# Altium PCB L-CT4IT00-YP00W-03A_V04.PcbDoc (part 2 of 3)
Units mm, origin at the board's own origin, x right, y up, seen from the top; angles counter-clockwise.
Board outline 52 x 31.8 mm, 4 copper layers (Top Layer, Layer 1, Layer 2, Bottom Layer), stack 1.288 mm thick; 160 components, 112 nets, 631 pads, 1087 vias.
Unrouted connection lines stored in the file: 130.
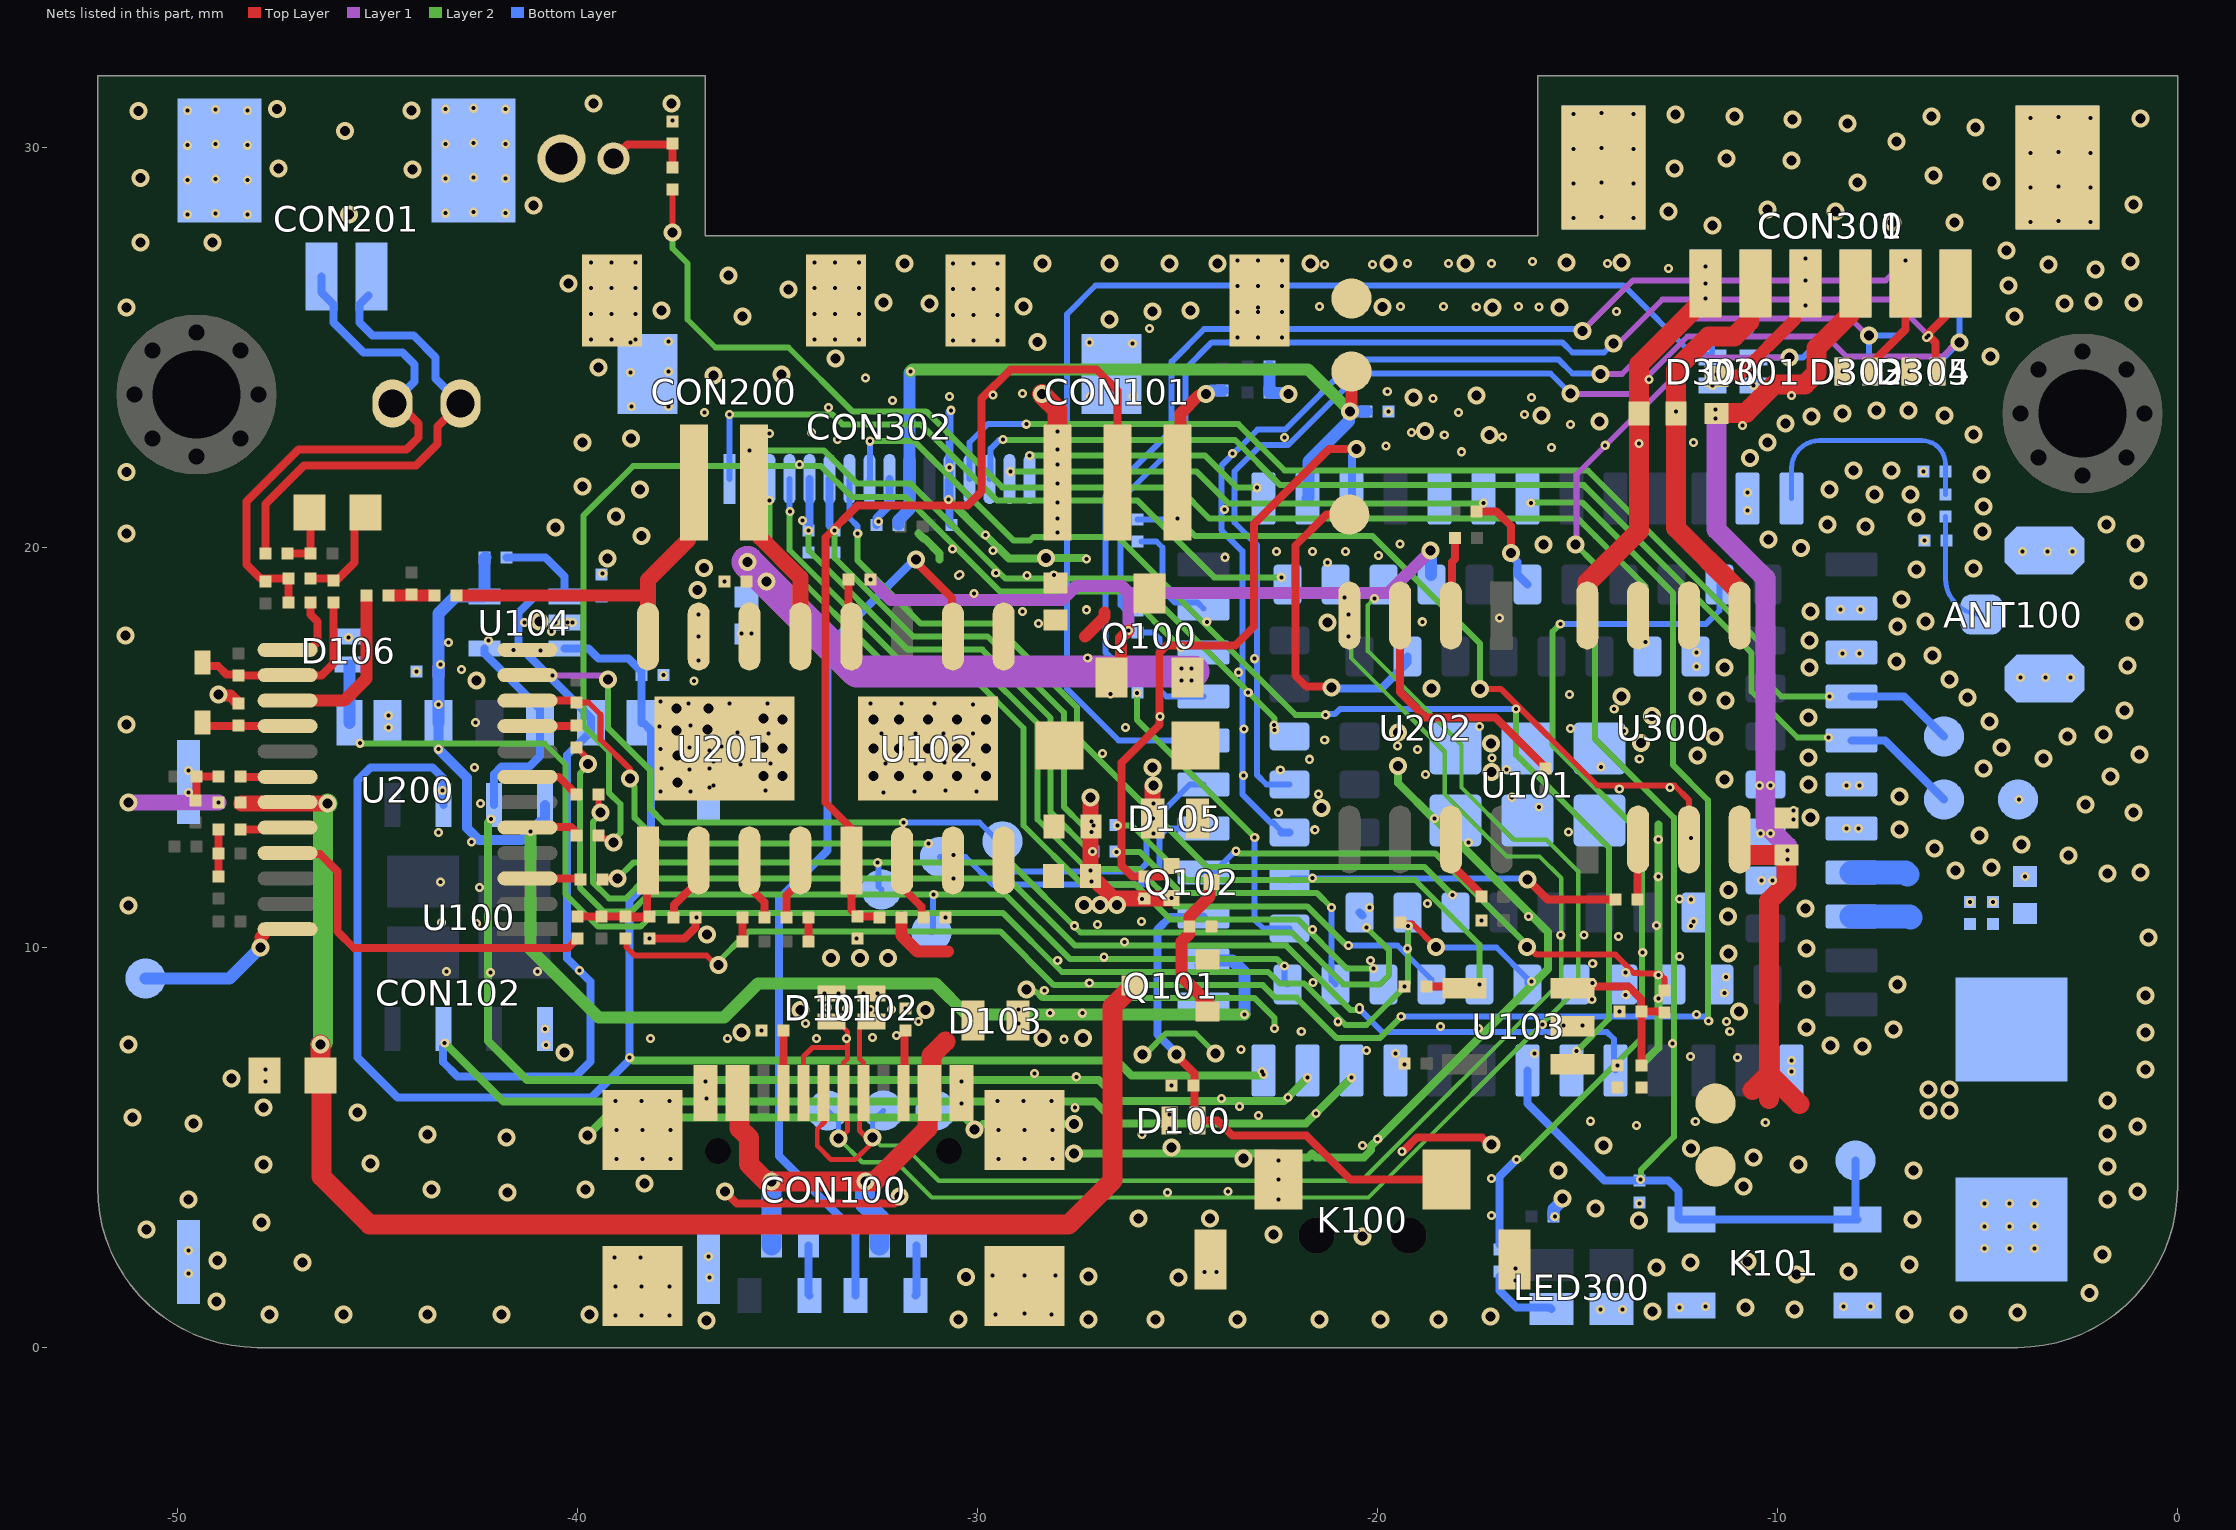
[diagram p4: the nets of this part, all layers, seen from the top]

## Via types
v1: diameter 0.23, hole 0.1, Top Layer to Layer 1, tented both sides, 385 vias
v2: diameter 0.45, hole 0.25, Top Layer to Bottom Layer, tented both sides, 379 vias
v3: diameter 0.23, hole 0.1, Layer 2 to Bottom Layer, tented both sides, 323 vias

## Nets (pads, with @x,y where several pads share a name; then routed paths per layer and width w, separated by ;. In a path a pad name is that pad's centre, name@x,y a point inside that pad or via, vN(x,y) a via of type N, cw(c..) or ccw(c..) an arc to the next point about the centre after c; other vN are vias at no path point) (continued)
GND: ANT100.2 ANT100.3 C100.1 C101.1 C102.2 C103.1 C104.1 C105.1 C106.1 C107.1 C109.1 C110.1 C111.1 C112.1 C113.1 C114.1 C115.1 C116.1 C117.1 C118.1 C202.1 C203.1 C204.1 C205.1 C206.1 C215.1 C218.2 C300.1 C301.1 C303.2 C304.1 C305.2 C306.2 C307.1 C308.1 CON100.0 CON100.A1B12 CON100.B1A12 CON101.0 CON101.3 CON102.0@-36.725,2.133 CON102.0@-36.725,14.132 CON102.0@-49.725,2.133 CON102.0@-49.725,14.132 CON102.5 CON200.0 CON201.0 CON300.0 CON300.4 CON301.0 CON301.1 CON301.3 CON302.0@-26.65,24.338 CON302.0@-38.25,24.338 CON302.9 CON302.12 D100.A D101.A D102.A D103.A D105.A D106.A D300.A D301.A D302.A D303.A D304.A D305.A K100.0@-16.575,2.2 K100.0@-24.175,2.2 K100.1 K101.1 K101.2 K300.1 LED300.2 Q102.S R107.2 R108.2 R109.2 R111.2 R114.1 R115.1 R117.1 R120.1 R208.1 TP300.1 TP301.1 TP302.1 TP303.1 U100.1 U101.1 U101.10 U101.27 U101.34 U101.36 U101.37 U101.40 U101.41 U101.45 U101.46 U101.47 U101.48 U101.70 U101.71 U101.72 U101.73 U101.88 U101.89 U101.90 U101.91 U101.92 U101.93 U101.94 U101.95 U102.0 U102.3 U103.2 U104.2 U200.12 U201.0 U201.7 U202.4 U300.6 U300.7 | length 83.4
  Top Layer w0.2: v1(-38.2,10.225) -37.325,10.225 -37.05,10.5 C202.1@-37.05,10.75 ; v2(-36.314,3.9) -36.017,3.603 -32.072,3.603 v2@-31.95,3.725 ; v1(-28.577,6.852) v1@-28.569,6.852 ; v2(-27.583,5.589) v2@-27.566,5.606 ; v1@-27.566,5.991 v1(-27.56,5.997) ; v1@-19.371,4.9 -19.371,4.906 -19.362,4.915 -19.353,4.915 -19.018,5.25 -17.392,5.25 -17.217,5.075 v2(-17.15,5.075)
  Top Layer w0.3: v2(-48.974,16.325) -48.945,16.296 -48.671,16.296 C204.1@-48.475,16.1 ; C304.1@-11.525,24.275 -11.494,24.306 -10.957,24.306 -9.55,25.713 -9.55,26.35 CON300.4@-9.3,26.6
  Top Layer w0.4: v2(-27.176,13.751) -27.176,11.801 -26.6,11.225 -25.161,11.225 v1(-25.15,11.236) ; D105.A@-25.621,13.226 -25.621,14.029 v2(-25.6,14.05)
  Top Layer w0.5: v2(-28.391,23.834) -28,23.443 CON101.3@-28,21.625 ; D105.A@-25.621,13.016 D105.A@-25.621,13.226
  Layer 1 w0.4: v2@-51.175,13.625 v1(-48.975,13.625)
  Layer 2 w0.15: v2(-28.775,8.95) -28.718,8.893 -28.538,8.893 -28.378,8.732 -23.07,8.732 -22.58,8.243 -22.58,7.98 v3(-22.575,7.975) ; v2@-25.754,7.386 -25.29,7.85 -24.55,7.85 v2(-24.05,7.35)
  Layer 2 w0.2: v2(-39.75,5.3) -39.297,5.753 -30.317,5.753 -30.014,5.45 -30.007,5.45 -29.868,5.589 v2(-27.583,5.589) ; v3@-32.804,24.247 v3(-32.798,24.241) ; -31.475,20.35 -31.351,20.226 -31.321,20.226 -30.949,19.854 -30.949,19.7 ; v3(-30.728,21.202) -29.847,20.321 -29.816,20.321 v3@-29.816,20.316 ; v3@-29.808,20.321 -29.209,19.723 -28.301,19.723 v2(-28.29,19.734) -27.306,19.735 -27.285,19.714 v3(-27.277,19.714) ; v2(-27.583,4.85) -22.575,4.85 -22.479,4.754 -21.731,4.754 -21.635,4.85 -21.54,4.754 -20.344,4.754 -20.164,4.934 -20.164,5.035 -19.996,5.203 v3(-19.996,5.211) -19.989,5.211 -15.74,9.46 -15.74,10.391 -18.565,13.217 v3@-18.585,13.217 ; v3@-26.685,16.343 v3(-26.679,16.337) ; v2(-19.483,14.532) -19.483,14.108 v3@-18.588,13.213 ; -13.4,7.075 -12.981,7.494 v3(-12.981,8.728) v3(-12.981,9.314) v3(-12.981,11.77) v3(-12.981,12.704) -12.976,12.71 -12.976,13.072
  Bottom Layer w0.2: C306.2@-32.525,20.563 -32.525,20.739 -32.2,21.064 CON302.9@-32.2,21.712 ; v3(-30.728,21.202) -30.728,21.684 CON302.12@-30.7,21.712 -30.7,20.787 -30.7,20.613 C305.2@-30.65,20.563 ; CON302.12@-30.7,21.712 -30.7,23.388 -30.664,23.423 v3(-30.664,23.431) ; CON301.0@-15.25,28.6 CON301.0@-14.35,29.5
  Bottom Layer w0.3: R114.1@-22.7,24.525 C112.1@-22.7,23.875 -22.687,23.862 -22.252,23.862 v2(-22.223,23.833) ; C303.2@-15.593,3.271 C303.2@-15.6,3.275 C303.2@-15.6,3.275 -15.6,3.459 -15.375,3.684 v2(-15.375,3.725)
  other v1: -39.05,0.8 -38.4,0.8 -37.7,0.8 -29.55,0.825 -28.15,0.825 -28.825,0.85 -39.05,1.525 -38.4,1.525 -37.7,1.525 -16.55,1.675 -29.625,1.8 -28.825,1.8 -28.05,1.8 -24.324,1.886 -24.02,1.886 -16.55,1.975 -39.075,2.25 -38.425,2.25 -17.15,3.3 -22.475,3.7 -25.25,3.875 -23.74,3.9 -22.475,4.2 -17.15,4.225 -22.475,4.675 -39.02,4.713 -38.37,4.713 -37.67,4.713 -29.48,4.713 -28.83,4.713 -28.13,4.713 -19.385,4.9 -20.379,5.048 -25.89,5.323 -39.02,5.437 -38.37,5.437 -37.67,5.437 -29.48,5.437 -28.83,5.437 -28.13,5.437 -25.2,5.475 -22.975,5.8 -25.2,5.825 -21.535,5.85 -23.45,6.025 -30.4,6.1 -39.045,6.162 -38.395,6.162 -37.695,6.162 -29.505,6.162 -28.855,6.162 -28.155,6.162 -36.775,6.225 -23.9,6.225 -22.235,6.25 -25.15,6.55 -47.8,6.65 -36.8,6.65 -30.4,6.65 -27.531,6.769 -22.885,6.9 -47.8,6.95 -14,7.05 -19.326,7.075 -11.001,7.25 -12.176,7.275 -16.075,7.35 -20.275,7.425 -23.41,7.45 -12.626,7.6 -27.836,7.706 -35.4,7.925 -17.476,7.975 -18.426,8.025 -15.35,8.05 -14.875,8.05 -15.876,8.075 -28.975,8.1 -20.987,8.145 -11.275,8.15 -12.025,8.325 -28.182,8.362 -27.38,8.358 -13.95,8.4 -28.975,8.45 -31.8,8.475 -20.451,8.5 -33.825,8.85 -33.475,8.85 -32.85,8.85 -32.5,8.85 -28.331,8.925 -19.325,9.025 -27.207,9.116 -21.615,9.125 -16.151,9.15 -42.175,9.375 -43.275,9.4 -41,9.4 -39.95,9.425 -27.995,9.677 -20.176,9.675 -26.839,9.758 -12.451,9.775 -13.371,9.876 -19.251,9.969 -26.324,10.136 -33.025,10.225 -13.976,10.275 -15.421,10.309 -14.837,10.316 -21.626,10.45 -27.577,10.542 -13.026,10.55 -27.002,10.574 -42.525,10.6 -43.4,10.625 -25.903,10.652 -12.101,10.65 -17.4,10.675 -37.025,10.75 -30.8,10.75 -16.226,10.775 -20.201,11 -18.751,11.1 -12.451,11.213 -25.891,11.218 -42.45,11.5 -43.425,11.636 -27.15,11.65 -30.6,11.725 -21.626,11.735 -27.175,11.925 -30.6,12.313 -42.649,12.639 -25.6,12.85 -43.475,12.875 -27.15,12.892 -21.568,12.943 -27.15,13.15 -9.6,13.2 -25.611,13.226 -22.476,13.375 -9.6,13.425 -42.425,13.6 -25.6,13.6 -21.473,13.834 -32.35,13.875 -37.925,13.9 -37.175,13.9 -31.575,13.9 -30.025,13.9 -43.375,13.925 -35.3,13.925 -30.8,13.925 -36.6,14.05 -23.351,14.3 -22.431,14.44 -37.2,14.45 -37.9,14.475 -42.575,14.5 -35.925,14.575 -30.1,14.575 -35.175,14.6 -32.3,14.6 -31.55,14.6 -30.825,14.625 -36.6,14.65 -21.7,14.705 -26.875,14.85 -43.475,14.957 -37.925,14.957 -37.2,15 -36.4,15.025 -35.225,15.35 -32.4,15.35 -31.55,15.35 -30.85,15.35 -30.11,15.35 -36,15.375 -23.336,15.467 -26.3,15.5 -37.95,15.525 -37.175,15.55 -22.586,15.563 -42.55,15.625 -43.475,16.075 -30.11,16.075 -37.225,16.1 -36.2,16.1 -35.25,16.1 -32.675,16.1 -31.9,16.1 -31.075,16.1 -37.925,16.15 -23.232,16.378 -23.479,16.881 -42.9,16.95 -43.425,17.075 -36.975,17.175 -23.078,17.222 -40.925,17.425 -41.6,17.442 -43.225,17.625 -42.225,17.675 -36.97,17.775 -20.726,17.775 -40.65,17.9 -41.325,18.125 -40.125,18.125 -24.269,18.143 -36.97,18.325 -20.726,18.325 -36.325,19.15 -28.762,19.304 -28.094,19.315 -30.437,19.329 -29.543,19.36 -21.251,19.625 -23.816,19.757 -19.976,19.8 -29.611,19.929 -30.626,19.963 -19.436,20.092 -28,20.375 -34.376,20.675 -28,20.725 -23.826,20.95 -28,21.125 -28,21.6 -30.701,22 -34.451,22.075 -28,22.075 -23.626,22.35 -28,22.45 -22.326,22.75 -28,22.9 -33.726,23.5 -32.126,23.675 -30.701,23.775 -11.525,24.325 -30.615,25.175 -30.1,25.175 -29.5,25.175 -39.665,25.2 -39.15,25.2 -38.55,25.2 -34.075,25.2 -33.56,25.2 -32.96,25.2 -23.5,25.25 -22.985,25.25 -22.385,25.25 -30.615,25.817 -30.1,25.817 -29.5,25.817 -39.665,25.842 -39.15,25.842 -38.55,25.842 -34.075,25.842 -33.56,25.842 -32.96,25.842 -23.5,25.892 -22.985,25.892 -22.385,25.892 -30.615,26.458 -30.1,26.458 -29.5,26.458 -39.665,26.483 -39.15,26.483 -38.55,26.483 -34.075,26.483 -33.56,26.483 -32.96,26.483 -23.5,26.533 -22.985,26.533 -22.385,26.533 -30.615,27.1 -30.1,27.1 -29.5,27.1 -39.665,27.125 -39.15,27.125 -38.55,27.125 -34.075,27.125 -33.56,27.125 -32.96,27.125 -23.5,27.175 -22.985,27.175 -22.385,27.175 -37.625,30.675
  other v2: -36.775,0.675 -30.475,0.7 -27.226,0.7 -25.55,0.7 -23.5,0.7 -21.45,0.7 -19.925,0.7 -18.475,0.7 -17.175,0.775 -47.7,0.825 -45.85,0.825 -43.75,0.825 -41.9,0.825 -39.7,0.825 -6.825,0.825 -5.475,0.825 -4,0.875 -13.125,0.9 -9.575,0.95 -10.8,1 -49.025,1.15 -2.2,1.36 -30.292,1.757 -24.98,1.751 -27.224,1.775 -9.525,1.825 -8.225,1.9 -13.025,2 -6.7,2.075 -12.18,2.12 -46.875,2.125 -49,2.175 -10.75,2.15 -1.875,2.325 -20.375,2.775 -22.6,2.825 -50.775,2.95 -47.9,3.125 -13.463,3.175 -6.625,3.2 -25.975,3.225 -24.184,3.219 -14.55,3.475 -49.725,3.7 -1.75,3.7 -31.95,3.78 -41.75,3.875 -1,3.9 -43.65,3.95 -39.804,3.95 -10.85,4.025 -38.325,4.1 -15.475,4.425 -6.6,4.425 -1.75,4.525 -47.85,4.575 -9.475,4.575 -45.175,4.6 -23.351,4.725 -10.6,4.75 -12.168,4.978 -25.15,5 -14.35,5.05 -41.775,5.25 -43.75,5.325 -1.75,5.35 -30.075,5.45 -1,5.525 -49.6,5.6 -51.125,5.75 -45.5,5.875 -47.85,6 -1.75,6.175 -48.65,6.725 -0.8,6.95 -25.875,7.325 -40.325,7.375 -7.875,7.525 -8.675,7.55 -51.225,7.575 -27.365,7.737 -28.375,7.741 -35.9,7.875 -0.8,7.875 -7.1,7.95 -9.275,8 -10.962,8.404 -34.425,8.441 -31.3,8.441 -0.8,8.8 -9.275,8.95 -7,9.075 -33.658,9.738 -32.943,9.733 -32.241,9.738 -11.226,9.856 -9.275,9.975 -0.725,10.25 -36.762,10.325 -11.235,10.771 -9.3,10.975 -51.225,11.051 -27.335,11.06 -26.94,11.06 -26.512,11.06 -11.225,11.44 -1.75,11.85 -0.925,11.875 -5.55,11.925 -4.65,12 -2.725,12.3 -6.075,12.475 -3.9,12.575 -4.95,12.8 -6.95,12.95 -9.175,13.25 -1.1,13.375 -21.4,13.483 -2.3,13.575 -51.225,13.625 -6.95,13.775 -9.225,14.075 -37.5,14.125 -11.325,14.2 -35.35,14.283 -34.881,14.283 -32.597,14.283 -31.965,14.283 -31.24,14.283 -30.515,14.283 -29.79,14.283 -1.675,14.275 -17.152,14.39 -4.85,14.475 -25.625,14.5 -3.35,14.725 -9.225,14.75 -12,14.795 -37.5,14.8 -0.95,14.825 -34.881,14.975 -32.597,14.975 -31.965,14.975 -31.24,14.975 -30.515,14.975 -29.79,14.975 -35.35,15 -4.4,15 -17.163,15.102 -13.417,15.108 -11.575,15.275 -2.75,15.275 -1.85,15.325 -19.483,15.377 -37.525,15.425 -36.75,15.45 -51.275,15.575 -4.7,15.65 -34.881,15.7 -32.597,15.7 -31.965,15.7 -31.24,15.7 -30.515,15.7 -29.79,15.7 -35.35,15.725 -9.225,15.751 -13.135,15.786 -1.325,15.925 -37.525,15.975 -36.725,15.975 -11.3,16.175 -5.25,16.25 -13.897,16.278 -12,16.275 -18.65,16.475 -42.525,16.675 -5.7,16.7 -11.325,17 -9.2,17 -1.25,17.05 -7.025,17.15 -6.125,17.3 -9.2,17.675 -51.3,17.8 -7,18.025 -21.25,18.125 -40.95,18.15 -6.3,18.15 -1.075,18.15 -9.175,18.4 -6.9,18.7 -37.002,18.942 -0.975,19.175 -6.525,19.45 -36.842,19.493 -5.1,19.475 -39.254,19.731 -9.416,19.987 -15.85,20.075 -1.05,20.1 -10.225,20.2 -38.402,20.292 -51.275,20.35 -4.875,20.4 -40.55,20.5 -7.8,20.525 -8.75,20.575 -1.775,20.575 -6.525,20.75 -39.041,20.772 -4.85,21.025 -7.575,21.325 -6.675,21.325 -38.441,21.45 -8.7,21.45 -39.875,21.525 -4.9,21.825 -51.281,21.884 -8.1,21.925 -7.15,21.925 -10.691,22.238 -39.875,22.625 -10.25,22.625 -38.658,22.727 -17.197,22.811 -5.1,22.825 -18.814,22.916 -9.8,23.1 -14.45,23.15 -9.15,23.275 -15.9,23.3 -5.825,23.3 -8.375,23.35 -7.525,23.425 -6.725,23.425 -19.1,23.75 -17.531,23.799 -36.6,24.3 -34.9,24.325 -39.475,24.5 -33.55,24.725 -4.675,24.775 -28.495,25.136 -26.7,25.7 -35.875,25.775 -4.075,25.775 -25.625,25.9 -37.9,25.925 -24.675,25.925 -15.445,25.996 -51.273,26.001 -28.855,26.025 -19.876,26.008 -17.123,26.002 -31.2,26.1 -2.825,26.1 -32.35,26.125 -1.1,26.125 -2.1,26.15 -34.725,26.45 -4.225,26.55 -40.225,26.6 -36.225,26.8 -2.05,26.95 -3.225,27.075 -31.825,27.1 -28.375,27.1 -26.7,27.1 -25.2,27.1 -24,27.1 -21.675,27.1 -19.725,27.1 -17.8,27.1 -15.275,27.125 -13.9,27.125 -1.175,27.15 -4.275,27.425 -50.929,27.62 -49.125,27.625 -11.625,28.05 -7.125,28.125 -5.575,28.125 -45.714,28.327 -12.725,28.4 -8.55,28.4 -10.25,28.45 -41.1,28.55 -1.1,28.575 -8,29.125 -4.65,29.15 -50.921,29.243 -6.1,29.3 -44.125,29.45 -47.475,29.475 -12.575,29.475 -9.65,29.675 -11.275,29.725 -7.025,30.15 -45.812,30.416 -5.05,30.5 -8.25,30.6 -9.625,30.7 -0.925,30.725 -11.075,30.775 -6.15,30.775 -12.55,30.825 -50.973,30.914 -44.15,30.925 -47.508,30.958 -39.6,31.1 -37.65,31.1
  other v3: -14.425,0.95 -13.875,0.95 -12.45,1 -11.8,1.025 -8.35,1.025 -7.675,1.025 -36.7,1.75 -49.725,1.85 -36.725,2.275 -49.725,2.425 -4.825,2.475 -4.2,2.475 -3.575,2.475 -4.825,3.025 -4.2,3.025 -3.575,3.025 -15.568,3.271 -13.45,3.6 -4.825,3.6 -4.2,3.6 -3.575,3.6 -13.524,5.551 -10.305,5.625 -12.055,5.65 -14.676,5.657 -9.65,6.9 -9.65,7.175 -19.55,7.35 -40.793,7.561 -38.175,7.725 -36.25,7.725 -34.025,7.725 -33.275,7.725 -32.625,7.75 -32.025,7.8 -21.905,7.898 -11.194,7.9 -40.813,7.961 -34.3,8.1 -31.475,8.15 -32.675,8.45 -32.15,8.45 -33.275,8.475 -33.75,8.5 -14.643,8.7 -13.797,8.819 -11.331,8.86 -14.626,9.108 -11.288,9.265 -13.797,9.371 -14.621,9.603 -12.164,10.541 -5.188,11.138 -4.613,11.138 -12.164,11.197 -10.4,11.675 -10.125,11.675 -3.813,11.775 -17.725,12.625 -12.164,12.734 -10.425,12.85 -10.175,12.85 -15.226,12.886 -8.275,12.975 -7.975,12.975 -18.575,13.226 -15.961,13.51 -3.963,13.7 -16.635,13.755 -49.725,13.875 -13.956,13.961 -36.7,14 -12.686,14.001 -10.45,14.05 -10.175,14.05 -8.275,14.05 -7.95,14.05 -18.8,14.325 -49.725,14.425 -16.775,14.45 -36.7,14.475 -14.412,14.518 -13.455,14.71 -17.141,14.735 -36.7,14.925 -19,14.95 -19.503,15.035 -21.321,15.185 -13.834,15.414 -15.175,15.475 -44.725,15.5 -17.45,15.525 -25.434,15.776 -44.725,15.8 -14.083,15.961 -15.2,16.325 -37.087,16.66 -3.925,16.75 -3.3,16.75 -2.675,16.75 -37.85,16.807 -44.025,16.9 -12.025,17.025 -27.244,17.239 -8.375,17.35 -7.95,17.35 -12.025,17.375 -45.725,17.75 -35.9,17.85 -35.65,17.85 -28.475,18.1 -40.55,18.125 -40.251,18.131 -18.88,18.143 -16.948,18.241 -28.875,18.4 -27.272,18.443 -8.425,18.45 -7.925,18.45 -30.087,18.851 -30.475,19.3 -39.37,19.352 -22.526,19.899 -21.626,19.899 -20.8,19.899 -3.875,19.901 -3.25,19.901 -2.625,19.901 -6.325,20.175 -29.802,20.316 -32.475,20.65 -10.75,20.925 -10.75,21.375 -6.35,21.9 -17.9,22.393 -15.65,22.503 -19.791,22.536 -14.307,22.555 -13.463,22.603 -12.1,22.625 -33.5,22.7 -16.879,22.766 -18.331,22.811 -35.2,22.85 -34.15,22.875 -19.15,22.875 -10.875,23.05 -15.175,23.075 -16.325,23.325 -36.825,23.375 -17.975,23.375 -19.725,23.4 -12.537,23.4 -38.65,23.525 -37.725,23.525 -18.613,23.725 -16.15,23.75 -27.178,23.775 -26.105,23.775 -29.61,23.811 -9.65,23.8 -28.878,23.848 -19.756,23.9 -11.625,24.05 -10.6,24.05 -13.213,24.197 -38.675,24.375 -37.725,24.4 -8.375,24.4 -6.7,24.4 -26.128,25.1 -38.675,25.125 -27.2,25.131 -37.725,25.15 -6.275,25.25 -25.7,25.475 -14.025,25.9 -22.99,25.995 -21.45,26.025 -19.425,26.025 -18.35,26.025 -17.531,26.013 -16.475,26.025 -15.96,26.014 -9.3,26.05 -11.8,26.225 -11.8,26.6 -9.3,26.675 -12.725,26.975 -11.8,27.025 -21.325,27.075 -20.125,27.075 -19.25,27.1 -18.225,27.1 -17.15,27.1 -14.25,27.1 -16.125,27.15 -9.3,27.225 -3.675,28.133 -2.175,28.133 -2.975,28.158 -15.1,28.233 -13.6,28.233 -14.4,28.258 -49.75,28.325 -48.25,28.325 -49.05,28.35 -43.3,28.358 -41.8,28.358 -42.6,28.383 -3.675,29 -2.175,29 -2.975,29.025 -15.1,29.1 -13.6,29.1 -14.4,29.125 -49.75,29.192 -48.25,29.192 -49.05,29.217 -43.3,29.225 -41.8,29.225 -42.6,29.25 -3.675,29.867 -2.175,29.867 -2.975,29.892 -15.1,29.967 -13.6,29.967 -14.4,29.992 -49.75,30.058 -48.25,30.058 -49.05,30.083 -43.3,30.092 -41.8,30.092 -42.6,30.117 -3.675,30.733 -2.175,30.733 -2.975,30.758 -15.1,30.833 -13.6,30.833 -14.4,30.858 -49.75,30.925 -48.25,30.925 -49.05,30.95 -43.3,30.958 -41.8,30.958 -42.6,30.983
GX8006_BOOT: R202.1 TP203.1 U101.80 | length 23.5
  Top Layer w0.15: R202.1@-39.375,11.7 -39.375,11.65 -39.275,11.75 -39.251,11.726 v2(-39.002,11.726)
  Layer 2 w0.15: v2(-39.002,11.726) -38.606,12.122 -29.172,12.122 -27.425,10.375 -22.145,10.375 -20.845,9.075 -19.948,9.075 -19.71,9.313 -19.71,9.935 v3(-20.275,10.5)
  Bottom Layer w0.15: v3(-32.497,12.122) -32.481,12.106 -32.481,11.531 TP203.1@-32.4,11.45
  Bottom Layer w0.2: U101.80@-20.45,10.875 U101.80@-20.373,10.798
GX8006_INT: R204.1 U101.5 | length 30.7
  Top Layer w0.15: R204.1@-39.475,13.825 -39.475,13.378 -39.472,13.375 v2(-39.425,13.375) ; R204.1@-39.475,13.874 R204.1@-39.452,13.851
  Layer 2 w0.15: v2@-39.435,13.375 -39.435,13.316 -39.615,13.137 -39.615,11.631 -39.209,11.226 -38.795,11.226 -38.29,11.73 -29.244,11.73 -27.561,10.047 -22.281,10.047 -20.677,8.443 v3@-20.46,8.443
  Bottom Layer w0.15: v3@-20.446,8.453 -19.881,7.888 -14.266,7.888 -14.089,7.712 -14.089,6.964 U101.5@-14.05,6.925
  other v3: -20.451,8.453
GX8006_POWER: Q102.G R120.2 U101.25 | length 17
  Top Layer w0.2: Q102.G@-25.15,12.036 -25.411,11.775 R120.2@-25.825,11.775 -26.125,11.775 -26.4,12.05 -26.4,14.621 -25.45,15.571 -25.45,16.123 -25.453,16.126 -25.453,17.374 -25.277,17.55 -24.229,17.55 -24.226,17.548 -23.558,17.548 -23.085,18.021 -23.085,20.59 -21.212,22.463 v2(-20.53,22.463)
  Bottom Layer w0.2: U101.25@-20.65,21.225 -20.638,21.237 -20.638,22.288 -20.53,22.395 v2(-20.53,22.463)
GX8006_REV: R203.1 U101.21 | length 26.4
  Top Layer w0.15: R203.1@-39.475,12.8 -39.4,12.725 -39.281,12.725 -39.177,12.621 v2(-39.096,12.621)
  Layer 2 w0.15: v2(-39.096,12.621) -39.096,12.688 -38.925,12.859 -38.925,13.582 -39.214,13.872 -39.214,14.909 -39.854,15.549 -39.854,20.796 -38.611,22.039 -33.917,22.039 -33.146,21.268 -31.809,21.268 -29.436,18.895 -26.314,18.895 v3(-24.916,17.497)
GX8006_RST: R205.1 TP200.1 U101.100 | length 24
  Top Layer w0.15: R205.1@-40.025,15 -39.793,14.768 -39.793,14.645 v2(-39.735,14.588)
  Layer 2 w0.15: v2(-39.735,14.588) -39.735,14.558 -39.943,14.35 -39.943,11.495 -39.345,10.898 -38.659,10.898 -38.23,11.326 -31.098,11.326 v3(-31.097,11.325) -29.303,11.325 -27.694,9.716 -22.523,9.716 -22.344,9.537 v3(-22.322,9.537)
  Bottom Layer w0.15: TP200.1@-31.15,10.384 -31.112,10.423 -31.112,11.31 v3(-31.097,11.325) ; v3(-22.322,9.537) -22.322,9.147 U101.100@-22.25,9.075
GX8006_RXD: TP202.1 U101.18 U200.11 | length 21.2
  Layer 1 w0.15: v1(-40.625,16.8) -39.422,16.8 -39.317,16.695 v2(-39.236,16.695)
  Layer 2 w0.15: v2(-39.236,16.695) -39.236,15.479 -38.185,14.428 -38.185,13.469 -37.841,13.125 v3(-31.852,13.126)
  Bottom Layer w0.15: v3(-31.852,13.126) -29.951,13.126 TP202.1@-29.6,12.775 ; TP202.1@-29.587,12.788 TP202.1@-29.463,12.788 ; TP202.1@-29.375,12.658 -29.348,12.631 -29.348,12.02 -29.228,11.901 -25.974,11.901 -25.778,12.097 -25.778,12.99 -24.693,14.075 U101.18@-24.35,14.075
GX8006_TXD: R206.1 TP201.1 U101.17 U200.10 | length 20.5
  Top Layer w0.15: R206.1@-40.025,16.125 -39.725,16.125 -39.425,15.825 -39.425,15.2 -38.685,14.46 v2(-38.685,14.221) v2@-38.734,14.27
  Top Layer w0.2: U200.10@-41.25,16.172 -40.073,16.172 R206.1@-40.025,16.125
  Layer 2 w0.15: v2(-38.685,14.221) -38.685,14.14 -38.57,14.025 -38.57,13.243 -37.927,12.6 v3(-31.225,12.6)
  Bottom Layer w0.15: TP201.1@-30.936,12.263 -30.299,12.263 -29.609,11.573 -25.802,11.573 -25.45,11.925 -25.45,12.775 -25.25,12.975 U101.17@-24.35,12.975
IO1: CON301.5 D303.K U101.55 | length 31.2
  Layer 1 w0.15: v2(-14.425,24.338) -13.888,24.338 -12.5,25.725 -8.175,25.725 -7.75,25.3 v2(-7.708,25.3)
  Bottom Layer w0.15: U101.55@-22.425,12.875 -22.425,12.934 -22.623,13.131 -22.681,13.131 -23.379,13.829 -23.379,19.908 -23.903,20.432 -23.903,22.042 -22.995,22.95 -22.308,22.95 -20.555,24.704 -15.479,24.704 -15.125,24.35 -14.437,24.35 v2(-14.425,24.338) ; D303.K@-7.675,24.4 -7.708,24.433 v2(-7.708,25.3) -7,25.3 -6.8,25.5 CON301.5@-6.8,26.6
  Bottom Layer w0.2: U101.55@-22.4,12.875 U101.55@-22.2,12.875
IO2: CON301.6 D305.K U101.56 | length 31.6
  Layer 1 w0.15: v2@-15.175,23.837 -13.688,23.837 -12.25,25.275 -8.775,25.275 -8.275,24.775 -5.875,24.775 -5.519,25.131 v2(-5.45,25.131)
  Bottom Layer w0.15: U101.56@-22.2,14.075 -22.775,14.075 -23.015,14.315 -23.015,20.065 -23.575,20.625 -23.575,21.906 -22.923,22.558 -22.237,22.558 -20.445,24.35 -15.675,24.35 v2(-15.175,23.85) ; D305.K@-6,24.4 -5.9,24.5 -5.9,24.681 v2(-5.45,25.131) -5.531,25.131 -5.45,25.213 -5.45,26.5 CON301.6@-5.55,26.6
KEY_BOOT: TP106.1 U101.82 | length 8.3
  Top Layer w0.2: v2(-21.15,16.506) -21.166,16.522 -21.775,16.522 -22.055,16.801 -22.055,20.045 -21.275,20.825 TP106.1@-20.705,20.825
  Bottom Layer w0.2: v2(-21.15,16.506) -21.119,16.475 -19.897,16.475 -19.25,17.122 U101.82@-19.25,17.275
KEY_FUNC: CON301.2 D300.K U101.19 | length 33.1
  Bottom Layer w0.15: U101.19@-24.35,15.175 -26.472,15.175 -27.761,16.464 -27.761,25.839 -27.05,26.55 -13.849,26.55 -12.112,24.813 -11.688,24.813 -11.679,24.804 D300.K@-11.625,24.75 ; D300.K@-11.634,24.85 -11.634,25.199 -11.517,25.317 -10.767,25.317 -10.65,25.434 -10.65,26.5 CON301.2@-10.55,26.6
LCD_CLK: C308.2 CON302.5 R123.1 | length 13.2
  Layer 2 w0.15: v3(-34.225,20.425) -34.225,19.928 -31.744,17.447 -29.88,17.447 -28.172,15.739 -28.172,13.383 -27.189,12.4 v3(-27.125,12.4)
  Bottom Layer w0.2: -34.2,20.575 CON302.5@-34.2,21.712
LCD_CS1: CON302.3 U101.52 | length 22.1
  Layer 2 w0.15: v3(-35.202,21.176) -35.202,20.102 -35.2,20.1 -35.2,19.975 -32.016,16.791 -30.152,16.791 -28.85,15.489 -28.85,13.05 -27.38,11.58 -26.058,11.58 -25.182,10.703 -21.995,10.703 -20.767,9.475 v3(-20.1,9.475)
LCD_CS2: CON302.2 U101.57 | length 16.9
  Layer 2 w0.15: v3(-35.7,22.429) -35.692,22.42 -33.834,22.42 -33.017,21.603 -31.681,21.603 -29.3,19.223 -26.068,19.223 -22.57,15.724 v3(-22.57,15.443)
  Bottom Layer w0.15: CON302.2@-35.7,21.712 v3(-35.7,22.429)
LCD_DC: CON302.4 U101.51 | length 23.8
  Layer 2 w0.15: v3(-34.689,20.903) -34.7,20.892 -34.7,19.939 -31.88,17.119 -30.016,17.119 -28.5,15.603 -28.5,13.2 -27.262,11.962 -25.977,11.962 -25.046,11.031 -21.759,11.031 -20.818,10.09 -20.788,10.09 -20.748,10.05 v3(-20.726,10.05)
  Bottom Layer w0.15: CON302.4@-34.7,21.712 -34.695,21.707 -34.695,20.908 v3(-34.689,20.903) ; v3(-20.726,10.05) -19.5,10.05 -18.65,9.2 U101.51@-18.65,9.075
LCD_DOUT: C307.2 CON302.6 R122.1 | length 12.6
  Layer 2 w0.15: v3(-33.575,20.425) -33.575,19.742 -31.608,17.775 -29.745,17.775 -27.844,15.874 -27.844,13.519 -27.375,13.05 v3(-27.1,13.05)
  Bottom Layer w0.2: CON302.6@-33.7,21.712 -33.7,20.55 v3(-33.575,20.425)
LCD_LED: CON302.1 U101.103 | length 17.1
  Layer 2 w0.15: v3(-36.2,23.325) -33.622,23.325 -33.374,23.077 -31.419,23.077 -29.519,21.177 -26.004,21.177 -24.082,19.255 v3(-22.406,19.255)
  Bottom Layer w0.15: CON302.1@-36.2,21.712 v3@-36.2,23.318
LCD_RST: CON302.7 U101.78 | length 20.9
  Layer 2 w0.15: v3(-32.995,20.35) -32.995,19.67 -31.428,18.103 -29.609,18.103 -27.516,16.01 -27.516,15.259 -24.272,12.015 -18.827,12.015 v3@-18.132,11.32
  Bottom Layer w0.15: CON302.7@-33.2,21.712 -33.2,20.739 -32.995,20.534 v3(-32.995,20.35)
  other v3: -18.126,11.313
LCD_TE: CON302.16 U101.23 | length 6
  Layer 2 w0.15: v3(-28.696,22.297) -24.311,22.297 -23.509,21.496 v3(-23.01,21.496)
LDO33_EN: R116.1 U101.16 | length 13.4
  Top Layer w0.15: v2(-16.265,10.017) -16.22,10.017 -16.027,9.824 -14.051,9.824 -13.588,9.36 -13.461,9.36 -13.456,9.355 -12.954,9.355 -12.825,9.227 R116.1@-12.825,8.925
  Layer 2 w0.15: v3@-23.539,12.398 -23.509,12.398 -23.459,12.348 -18.548,12.348 -16.33,10.13 v2@-16.33,9.962
  Bottom Layer w0.15: U101.16@-24.35,11.875 -24.092,11.875 -23.575,12.392 -23.555,12.392 v3(-23.539,12.407)
M+: C302.2 CON300.6 U300.8 | length 9.6
  Top Layer w0.5: U300.8@-14.755,18.3 -14.745,18.31 -14.745,19.13 -13.463,20.412 C302.2@-13.463,23.35 -13.463,24.574 -12.037,26 -11.95,26 -11.8,26.15 CON300.6@-11.8,26.6
M-: C302.1 CON300.5 U300.5 | length 9.9
  Top Layer w0.5: U300.5@-10.945,18.3 -10.945,18.889 -10.97,18.914 -10.97,18.92 -12.537,20.488 C302.1@-12.537,23.35 -12.537,24.461 -11.724,25.275 -11.081,25.275 -10.7,25.656 -10.7,26.35 CON300.5@-10.65,26.4
MIC1: C213.2 U200.15 | length 4.6
  Top Layer w0.3: U200.15@-47.697,16.175 -45.825,16.175 -45.275,16.725 C213.2@-45.275,18.7
MIC_N: CON201.2 MIC200.2 R217.2 | length 11.9
  Top Layer w0.2: R217.2@-47.8,19.85 -47.8,21.09 -46.84,22.05 -44.035,22.05 -43.5,22.585 -43.5,23.025 MIC200.2@-42.925,23.6
  Bottom Layer w0.2: CON201.2@-45.225,26.3 -45.45,26.075 -45.45,25.625 -45.125,25.3 -44.096,25.3 -43.55,24.754 -43.55,24.225 MIC200.2@-42.925,23.6
MIC_P: C208.1 C209.1 CON201.1 MIC200.1 R214.2 | length 14.5
  Top Layer w0.2: C208.1@-47.225,18.625 R214.2@-47.225,19.225 -47.925,19.225 -48.275,19.575 -48.275,21.15 -46.975,22.45 -44.275,22.45 -43.975,22.75 -43.975,23.1 -44.475,23.6 MIC200.1@-44.625,23.6
  Bottom Layer w0.2: CON201.1@-46.4,26.775 -46.4,26.375 -46.1,26.075 -46.1,25.625 -45.35,24.875 -44.375,24.875 -44.075,24.575 -44.075,24.15 MIC200.1@-44.625,23.6
NetANT100_1: ANT100.1 C108.1 C109.2 | length 3
  Bottom Layer w0.12: C108.1@-5.8,20.775 -5.8,19.225 ccw(c-4.9,19.225) ANT100.1@-4.9,18.325
NetC100_2: C100.2 D100.K K100.2 U101.15 | length 13.2
  Top Layer w0.2: v2(-25.025,7.325) -25.025,7.3 -24.575,6.85 -24.575,5.925 -24.525,5.875 D100.K@-24.525,5.725 ; D100.K@-24.5,5.675 -24.004,5.675 -23.629,5.3 -21.78,5.3 -20.68,4.2 K100.2@-18.275,4.2
  Bottom Layer w0.2: v2(-25.025,7.325) -25.025,7.352 -25.5,7.827 -25.5,10.451 -25.183,10.768 -24.357,10.768 U101.15@-24.35,10.775
NetC107_2: C107.2 C108.2 U101.35 | length 6.1
  Bottom Layer w0.12: U101.35@-9.65,21.225 -9.65,21.975 cw(c-8.95,21.975) -8.95,22.675 -6.4,22.675 cw(c-6.4,22.075) -5.8,22.075 ; C108.2@-5.8,21.325 C107.2@-5.8,21.9 -5.8,22.05
NetC114_2: C114.2 U103.4 | length 1
  Top Layer w0.2: C114.2@-18.775,9.025 -17.865,9.025 U103.4@-17.825,8.985
NetC200_2: C200.2 R209.1 | length 0.6
  Top Layer w0.2: C200.2@-34.225,10.15 R209.1@-34.225,10.75
NetC201_2: C201.2 R210.1 | length 0.6
  Top Layer w0.2: C201.2@-35.875,10.15 R210.1@-35.875,10.75
NetC202_2: C202.2 U201.2 | length 1.7
  Top Layer w0.2: C202.2@-37.6,10.75 -37.588,10.762 -37.588,11.062 -36.97,11.68 U201.2@-36.97,12.175 U201.2@-36.95,12.155
NetC204_2: C204.2 D200.A U200.16 | length 2.2
  Top Layer w0.2: D200.A@-49.375,15.625 -49.288,15.537 U200.16@-47.25,15.537
NetC207_2: C207.2 D200.K R211.2 U200.14 | length 5
  Top Layer w0.2: D200.K@-49.375,17.125 -49.292,17.042 -48.992,17.042 -48.775,16.825 -48.5,16.825 C207.2@-48.475,16.8 -47.257,16.8 U200.14@-47.25,16.807 ; U200.14@-47.186,16.802 -46.398,16.802 -46.1,17.1 R211.2@-46.1,18.625
NetC208_2: C208.2 U200.13 | length 2.5
  Top Layer w0.2: U200.13@-47.775,17.368 U200.13@-47.25,17.368 ; U200.13@-47.25,17.442 -46.692,17.442 -46.5,17.635 -46.5,18.15 -46.675,18.325 C208.2@-46.675,18.625 C208.2@-46.625,18.575
NetC210_1: C210.1 R212.1 R215.1 | length 1.2
  Top Layer w0.2: R212.1@-48.979,12.946 C210.1@-48.979,12.346 -48.979,11.796 R215.1@-48.954,11.771
NetC211_1: C211.1 R213.1 R216.2 | length 1.2
  Top Layer w0.2: R216.2@-49.55,13.675 -49.525,13.7 C211.1@-49.525,14.275 -49.521,14.271 R213.1@-48.979,14.271
NetC212_1: C212.1 R217.1 R218.2 | length 1.6
  Top Layer w0.2: R217.1@-47.25,19.85 R218.2@-46.65,19.85 ; C212.1@-46.7,20.875 -46.675,20.85 R218.2@-46.675,19.875
NetC212_2: C212.2 R211.1 R214.1 | length 2.7
  Top Layer w0.2: R214.1@-46.675,19.225 -46.15,19.225 R211.1@-46.1,19.175 -46.025,19.175 -45.575,19.625 -45.575,20.6 C212.2@-45.3,20.875
NetC213_1: C213.1 R221.2 R224.1 | length 1.2
  Top Layer w0.3: C213.1@-44.725,18.8 R221.2@-43.575,18.8
NetC301_2: C301.2 K300.2 R300.2 | length 2.2
  Top Layer w0.2: K300.2@-39.1,29.725 -38.75,30.075 C301.2@-37.625,30.075 ; R300.2@-37.625,29.5 C301.2@-37.625,30.075 ; C301.2@-37.625,30.1 C301.2@-37.625,30.075
NetCON100_A5: CON100.A5 R108.1 | length 1.6
  Top Layer w0.2: CON100.A5@-34.85,6.363 R108.1@-34.85,7.925
NetCON100_B5: CON100.B5 R109.1 | length 1.6
  Top Layer w0.2: CON100.B5@-31.85,6.363 -31.825,6.387 R109.1@-31.825,7.925
NetCON101_2: CON101.2 R110.2 R111.1 U102.1 | length 23
  Top Layer w0.2: R111.1@-33.025,10.775 R110.2@-32.55,10.775 ; R111.1@-32.995,10.775 -33.155,10.935 -33.155,12.98 -33.795,13.62 -33.795,20.255 -33,21.05 -30.25,21.05 -29.9,21.4 -29.9,23.725 -29.179,24.446 -27.021,24.446 -26.5,23.925 CON101.2@-26.5,21.85
NetCON200_1: CON200.1 U201.5 | length 4.3
  Top Layer w0.4: CON200.1@-35.585,21.625 -35.435,21.475 -35.435,20.251 -34.43,19.246 U201.5@-34.43,17.775
NetLED300_3: LED300.3 R301.1 | length 1.8
  Bottom Layer w0.2: R301.1@-16.95,1.775 -16.95,1.425 -16.525,1 -15.691,1 LED300.3@-15.65,0.959
NetLED301_A: LED301.A R302.1 | length 1.3
  Bottom Layer w0.2: R302.1@-34.225,2.55 -34.225,1.325 LED301.A@-34.2,1.3
NetLED302_A: LED302.A R303.2 | length 1.3
  Bottom Layer w0.2: LED302.A@-31.55,1.3 -31.525,1.325 R303.2@-31.525,2.55
NetQ101_G: Q101.G Q102.D R119.2 | length 4.3
  Top Layer w0.3: Q101.G@-24.25,8.4 -24.3,8.4 -24.4,8.5 -24.4,8.777 ; Q102.D@-24.15,11.636 -24.2,11.586 -24.2,11.27 -24.7,10.77 R119.2@-24.7,10.525 -24.7,10.345 -24.9,10.145 -24.9,9.277 -24.4,8.777 ; Q101.G@-24.113,8.49 -24.4,8.777
NetR101_1: R101.1 U101.22 | length 2.9
  Bottom Layer w0.15: R101.1@-25.9,20.15 -25.525,20.15 -25.375,20 -25.375,18.937 -25.057,18.62 -24.495,18.62 U101.22@-24.35,18.475
NetR102_1: R102.1 U101.101 | length 7.9
  Layer 2 w0.15: v3(-26.017,16.365) -26.017,15.697 v3(-23.071,12.751)
  Bottom Layer w0.15: v3(-23.071,12.751) -23.071,10.696 -22.85,10.475 U101.101@-22.2,10.475
NetR104_1: R104.1 U101.63 | length 2.6
  Top Layer w0.2: R104.1@-17.525,20.9 -17.025,20.9 -16.658,20.533 v2(-16.658,19.868)
  Bottom Layer w0.2: v2(-16.658,19.868) -16.658,19.801 -16.497,19.639 -16.497,19.322 U101.63@-16.25,19.075
NetR105_1: R105.1 U101.54 | length 8.5
  Top Layer w0.2: v2@-16.299,11.701 v2(-16.251,11.701) ; v2@-16.3,11.701 -16.276,11.726 v2@-16.25,11.7 ; R105.1@-14.05,11.2 -15.75,11.2 v2@-16.25,11.7
  Bottom Layer w0.15: U101.54@-22.2,11.675 -22.15,11.725 v2@-16.2,11.725
NetR106_1: R106.1 U102.8 | length 1.5
  Top Layer w0.2: R106.1@-33.222,19.2 -33.222,17.842 U102.8@-33.155,17.775
NetR107_1: R107.1 U102.2 | length 1.6
  Top Layer w0.2: U102.2@-31.885,12.175 -31.885,11.505 -31.4,11.02 -31.4,10.8 R107.1@-31.35,10.75
NetR112_1: R112.1 U101.49 | length 3.9
  Top Layer w0.15: R112.1@-19.425,10.625 -19.4,10.6 -19.132,10.6 v2(-18.54,10.008)
  Bottom Layer w0.15: v2@-18.54,10 -17.026,10 -16.25,9.224 U101.49@-16.25,9.075
NetR116_2: R116.2 R117.2 R118.2 U103.3 | length 4.1
  Top Layer w0.2: U103.3@-15.125,8.985 -15.085,9.025 -13.721,9.025 -13.41,8.714 -13.41,8.41 R117.2@-13.4,8.4 ; R118.2@-13.4,7.05 R117.2@-13.4,8.4 ; R116.2@-12.825,8.375 -12.85,8.4 R117.2@-13.4,8.4
NetR122_2: R122.2 U101.50 | length 11.3
  Layer 2 w0.15: v3(-26.501,13.051) -26.138,13.051 -24.774,11.687 -19.062,11.687 -17.45,10.075 v3(-17.45,9.075)
NetR123_2: R123.2 U101.53 | length 7.9
  Layer 2 w0.15: v3(-26.525,12.385) -25.936,12.385 -24.91,11.359 -21.509,11.359 v3(-21.15,11)
  Bottom Layer w0.15: v3(-21.15,11) -21.15,9.175 U101.53@-21.05,9.075
NetR124_2: R124.2 U101.20 | length 2.9
  Bottom Layer w0.15: R124.2@-25.875,17.875 -25.6,17.875 -25.45,17.725 -25.45,16.45 -25.275,16.275 U101.20@-24.35,16.275
NetR200_1: R200.1 R201.2 R207.1 R208.2 U201.1 | length 3.6
  Top Layer w0.2: R200.1@-40,10.775 R207.1@-39.4,10.775 R208.2@-38.258,10.775 ; R201.2@-38.675,10.75 -38.258,10.75 R208.2@-38.258,10.775 ; U201.1@-38.24,12.175 -38.258,12.157 R208.2@-38.258,10.775 ; R208.2@-38.2,10.775 R208.2@-38.258,10.775
NetR202_2: R202.2 U200.3 | length 1.3
  Top Layer w0.2: U200.3@-41.25,11.727 -39.953,11.727 R202.2@-39.925,11.7
NetR203_2: R203.2 U200.5 | length 1.3
  Top Layer w0.2: U200.5@-41.231,13.017 U200.5@-41.01,13.017 ; U200.5@-41.018,13.009 U200.5@-41.01,13.017 ; U200.5@-40.999,13.028 U200.5@-41.01,13.017 ; R203.2@-40.025,12.875 -40.167,13.017 U200.5@-41.01,13.017
NetR204_2: R204.2 U200.7 | length 1.4
  Top Layer w0.2: U200.7@-41.25,14.267 -40.468,14.267 R204.2@-40.025,13.825
NetR205_2: R205.2 U200.9 | length 1.2
  Top Layer w0.2: U200.9@-41.25,15.537 -40.038,15.537 R205.2@-40.025,15.55
NetR209_2: R209.2 U201.4 | length 1.6
  Top Layer w0.2: R209.2@-34.775,10.75 -34.775,11.308 -34.43,11.653 U201.4@-34.43,12.175
NetR210_2: R210.2 U201.3 | length 1.6
  Top Layer w0.2: U201.3@-35.7,12.175 -35.7,11.508 -35.325,11.133 R210.2@-35.325,10.75
NetR212_2: R212.2 U200.20 | length 1.2
  Top Layer w0.2: R212.2@-48.429,12.946 -47.917,12.946 -47.866,12.997 U200.20@-47.25,12.997
NetR213_2: R213.2 U200.18 | length 1.2
  Top Layer w0.2: R213.2@-48.475,14.275 -48.468,14.267 U200.18@-47.25,14.267
NetR219_2: R219.2 U202.2 | length 2
  Top Layer w0.2: U202.2@-18.165,18.3 -18.142,18.323 -18.142,19.633 -18.063,19.712 R219.2@-18.063,20.238
NetR220_2: R220.2 U202.3 | length 6.4
  Top Layer w0.2: U202.3@-19.435,18.3 -19.435,16.385 -18.8,15.75 -17.05,15.75 -15.8,14.5 R220.2@-15.8,14.475
NetR222_1: R222.1 U202.7 | length 1.8
  Top Layer w0.2: U202.7@-18.165,12.7 -18.165,12.09 R222.1@-17.35,11.275
NetTP204_1: TP204.1 U200.24 | length 4.2
  Top Layer w0.3: v2(-47.925,10) -47.925,10.25 -47.718,10.457 U200.24@-47.25,10.457
  Bottom Layer w0.3: TP204.1@-50.8,9.225 -48.7,9.225 v2(-47.925,10)
PA_CTL: R200.2 U200.21 | length 9.2
  Top Layer w0.2: U200.21@-47.25,12.362 -47.221,12.334 -46.434,12.334 -46,11.9 -46,10.4 -45.582,9.982 -40.242,9.982 R200.2@-40,10.225
PA_SD: R201.1 U101.29 | length 44.8
  Top Layer w0.15: R201.1@-38.8,10.225 -38.775,10.2 -38.775,10.008 -38.567,9.8 -36.776,9.8 -36.575,9.599 v2@-36.575,9.525
  Layer 2 w0.15: v2@-36.575,9.55 -35.723,10.402 -29.435,10.402 -28.093,9.06 -22.868,9.06 -22.554,8.746 -22.028,8.746 -21.017,7.735 -19.942,7.735 -19.407,8.27 v3(-19.407,8.278) ; v3(-16.168,21.115) -16.154,21.129 -14.885,21.129 -12.611,18.855 -12.611,14.558 -11.74,13.687 v3@-11.74,8.161
  Bottom Layer w0.15: v3(-19.407,8.278) -11.837,8.278 v3(-11.719,8.161)
  other v2: -36.479,9.568
PWM0: R101.2 U300.3 | length 18.4
  Top Layer w0.15: v2(-17.436,16.459) -16.909,16.459 -14.5,14.05 -12.575,14.05 -12.215,13.69 U300.3@-12.215,12.7
  Layer 2 w0.15: v3(-25.002,20.727) -24.566,20.291 -20.128,20.291 -17.436,17.599 v2(-17.436,16.459)
  Bottom Layer w0.15: R101.2@-26,20.7 -25.05,20.7 -25.024,20.727 v3(-25.002,20.727)
PWM1: CON300.2 D302.K R102.2 | length 30.9
  Top Layer w0.2: D302.K@-7.675,24.4 -7.675,24.575 -6.8,25.45 CON300.2@-6.8,26.6
  Layer 1 w0.15: v2(-14.876,25.417) -13.618,26.675 -7.3,26.675 v1@-6.798,27.177
  Bottom Layer w0.15: R102.2@-26,16.925 -26.018,16.907 -26.331,16.907 -26.797,17.373 -26.797,21.279 -25.147,22.929 -25.147,24.649 -24.339,25.457 -14.916,25.457 v2(-14.876,25.417)
  other v1: -6.8,27.175
PWM2: R105.2 U300.2 | length 1.5
  Top Layer w0.2: R105.2@-13.5,11.2 -13.5,12.685 U300.2@-13.485,12.7
PWM4: CON300.1 D304.K R124.1 | length 30.4
  Top Layer w0.2: D304.K@-6.091,24.15 D304.K@-6.041,24.2 ; D304.K@-6,24.4 -6.05,24.45 -6.05,25.125 -6.25,25.325 -5.55,26.025 CON300.1@-5.55,26.6 -5.808,26.342 CON300.1@-5.808,25.867
  Layer 1 w0.15: v2(-14.1,25.1) -13.975,25.1 -12.875,26.2 -7.125,26.2 v1@-6.25,25.325
  Bottom Layer w0.15: R124.1@-26,18.425 -26.009,18.434 -26.291,18.434 -26.425,18.568 -26.425,21.187 -24.8,22.812 -24.8,24.471 -24.142,25.129 -15.379,25.129 -15.125,24.875 -14.338,24.875 -14.113,25.1 v2(-14.1,25.1)
  other v1: -6.225,25.3
PWRKEY: C101.2 CON301.4 D301.K K101.3 K101.4 TP100.1 U101.7 | length 41.3
  Layer 1 w0.15: v2@-15.025,20.075 -15.025,21.825 -12.1,24.75 v2(-9.7,24.75)
  Layer 2 w0.15: v2(-15.05,20.075) -14.566,19.591 -14.566,15.223 -12.591,13.249 -12.591,5.262 -13.41,4.443 -13.41,4.215 v3(-13.425,4.2)
  Bottom Layer w0.15: D301.K@-10.6,24.75 v2(-9.7,24.75) -9.696,24.754 -9.361,24.754 -8.35,25.765 -8.35,26.3 CON301.4@-8.05,26.6
  Bottom Layer w0.2: U101.7@-16.25,6.925 -16.25,6.1 -14.325,4.175 -12.725,4.175 -12.475,3.925 -12.475,3.24 -12.43,3.195 K101.3@-12.155,3.195 K101.4@-8.005,3.195 -8.05,3.24 TP100.1@-8.05,4.675
RGB_LED: R301.2 U101.67 | length 22.8
  Layer 2 w0.15: v3(-16.525,4.7) -16.51,4.715 -16.42,4.715 -13.386,7.75 -13.386,12.819 -15.625,15.058 -15.625,17.895 v3(-15.43,18.09)
  Bottom Layer w0.15: v3(-15.43,18.09) -11.785,18.09 -11.45,18.425 U101.67@-11.45,19.075
  Bottom Layer w0.2: R301.2@-16.95,2.575 -16.95,4.275 v3(-16.525,4.7)
SHAKE: R300.1 U101.87 | length 31.5
  Top Layer w0.15: v2(-37.625,27.875) R300.1@-37.625,28.95
  Layer 2 w0.15: v2(-37.625,27.875) -37.625,27.48 -37.25,27.105 -37.25,25.7 -36.55,25 -34.725,25 -33.13,23.405 -31.283,23.405 -29.383,21.505 -24.983,21.505 -24.203,20.725 -14.996,20.725 -14.846,20.575 -14.843,20.575 -14.55,20.282 -14.55,20.279 -13.3,19.029 v3@-13.3,17.632
  other v3: -13.298,17.632
SPKP: CON200.2 R221.1 U201.8 | length 9
  Top Layer w0.3: R221.1@-42.925,18.8 -38.265,18.8 -38.24,18.775
  Top Layer w0.4: U201.8@-38.24,17.775 -38.24,18.775 -38.24,19.185 -37.235,20.19 -37.235,21.475 CON200.2@-37.085,21.625
STDBY_LED: LED302.K U102.6 | length 22.9
  Top Layer w0.2: v2(-31.539,19.701) -31.539,19.639 -30.639,18.739 -30.639,17.799 U102.6@-30.615,17.775
  Bottom Layer w0.2: LED302.K@-33.05,1.3 -33.05,2.875 -34.961,4.786 -34.961,11.215 -33.75,12.426 -33.75,17.527 -31.576,19.701 v2(-31.539,19.701)
TP_INT: CON302.8 U101.6 | length 29.9
  Layer 2 w0.15: v3(-32.686,22.659) -31.584,22.659 -29.102,20.177 -28.688,20.177 -28.603,20.262 -26.495,20.262 -22.05,15.817 v3(-21.297,15.817) ; v3(-16.535,15.961) -16.535,14.816 -14.214,12.496 -14.214,8.217 v3(-15.024,7.408)
  Bottom Layer w0.15: CON302.8@-32.7,21.712 -32.693,21.72 -32.693,22.652 v3(-32.686,22.659) ; v3(-21.297,15.817) -21.281,15.833 -21.07,15.833 -20.943,15.959 -16.537,15.959 v3(-16.535,15.961)
TP_RST: CON302.15 U101.28 | length 12.2
  Layer 2 w0.15: v3(-29.179,21.896) -24.522,21.896 -23.729,21.103 -17.362,21.103 v3(-17.35,21.115)
TP_SCL: CON302.14 TP101.1 U101.39 | length 28.4
  Layer 2 w0.15: v3(-29.361,22.697) -29.351,22.688 -23.56,22.688 -22.433,21.56 -14.841,21.56 -10.65,17.369 -10.65,16.4 -9.5,15.25 v3(-8.725,15.251)
  Bottom Layer w0.15: CON302.14@-29.7,21.712 -29.671,21.741 -29.671,22.471 -29.46,22.682 -29.376,22.682 v3(-29.361,22.697)
  Bottom Layer w0.2: U101.39@-8.15,15.175 -7.313,15.175 TP101.1@-5.838,13.7
TP_SDA: CON302.13 TP102.1 U101.38 | length 28.6
  Layer 2 w0.15: v3(-28.779,23.083) -23.48,23.083 -22.322,21.926 -14.743,21.926 -10.225,17.408 -10.225,16.6 -9.9,16.275 v3(-8.7,16.275)
  Bottom Layer w0.15: CON302.13@-30.2,21.712 -30.2,22.625 -29.738,23.087 -29.171,23.087 -29.167,23.083 v3(-28.779,23.083)
  Bottom Layer w0.2: U101.38@-8.15,16.275 -6.838,16.275 TP102.1@-5.838,15.275
USB_D_N: CON100.A7 CON100.B7 D101.K TP103.1 U101.60 | length 40.2
  Top Layer w0.12: CON100.B7@-34.35,6.363 -34.35,7.275 -34.125,7.5 -33.275,7.5 ; D101.K@-33.65,8.146 -33.5,8.146 -33.249,7.895 -33.249,7.224 -33.35,7.123 CON100.A7@-33.35,6.363 ; v2(-33.477,5.225) -33.441,5.225 v2@-33.416,5.25 ; v2@-33.382,5.216 v2@-33.416,5.25 ; CON100.A7@-33.382,5.764 CON100.A7@-33.35,5.796 ; CON100.A7@-33.29,6.422 CON100.A7@-33.35,6.363 ; v2@-33.416,5.25 -33.249,5.417 -33.249,5.649 -33.35,5.75 CON100.A7@-33.35,5.796 ; CON100.A7@-33.35,5.796 CON100.A7@-33.35,6.363
  Layer 2 w0.11: v2(-33.477,5.225) -32.881,4.63 -32.024,4.63 -31.144,3.75 -20.225,3.75 -15.106,8.869 -14.983,8.992 -14.983,11.903 -15.106,12.026 -15.775,12.695 -16.595,12.695 -17.9,14 -17.9,15.071 -20.24,17.411 -20.24,18.56 v3(-20.075,18.725)
  Bottom Layer w0.12: TP103.1@-33.75,5.925 -33.477,5.652 v2(-33.477,5.225)
USB_D_P: CON100.A6 CON100.B6 D102.K TP104.1 U101.59 | length 40.1
  Top Layer w0.12: CON100.A6@-33.898,5.764 -33.898,6.314 CON100.A6@-33.85,6.363 ; CON100.A6@-33.825,6.275 -33.825,5.638 -34.005,5.459 -34.005,5.041 -33.981,5.018 -33.981,5.016 -33.665,4.7 -33.054,4.7 v2@-32.659,5.096 ; CON100.B6@-32.909,6.422 CON100.B6@-32.85,6.363 ; v2@-32.692,5.129 -32.658,5.163 -32.625,5.196 v2(-32.625,5.25) -32.775,5.25 -32.951,5.426 -32.951,5.699 -32.85,5.8 CON100.B6@-32.85,6.363 ; D102.K@-32.65,8.146 -32.8,8.146 -32.951,7.995 -32.951,7.224 -32.85,7.123 CON100.B6@-32.85,6.363
  Layer 2 w0.11: v2(-32.625,5.25) -32.425,5.05 -31.85,5.05 -30.97,4.17 -20.399,4.17 -15.403,9.166 -15.403,11.729 -15.949,12.275 -16.769,12.275 -18.32,13.826 -18.32,14.897 -20.66,17.237 -20.66,18.585 v3(-20.825,18.75)
  Bottom Layer w0.12: v2(-32.625,5.25) -32.625,5.65 TP104.1@-32.35,5.925
USIM_CLK: C117.2 CON102.3 U100.6 U101.13 U104.3 | length 45.7
  Layer 2 w0.2: v3(-38.696,7.246) -38.688,7.246 -38.618,7.176 -26.523,7.176 -26.148,6.8 -22.875,6.8 v3(-22.85,6.825)
  Bottom Layer w0.2: U100.6@-43.353,13.561 -43.353,14.229 -43.624,14.5 -45.175,14.5 -45.5,14.175 -45.5,7.25 -44.5,6.25 -39.648,6.25 -38.702,7.196 -38.702,7.24 v3(-38.696,7.246) -38.696,11.179 -38.16,11.715 -38.16,15.427 CON102.3@-38.35,15.617 ; U104.3@-40.325,17.475 -39.725,17.475 -39.475,17.225 -38.725,17.225 -38.4,16.9 C117.2@-38.4,16.807 ; C117.2@-38.4,16.725 -38.395,16.72 CON102.3@-38.395,15.617
USIM_DATA: C118.2 CON102.7 R121.1 U100.3 U101.11 U104.1 | length 45.3
  Layer 2 w0.2: v3(-43.32,7.611) -41.853,6.145 -27.07,6.145 -26.531,5.606 -21.791,5.606 v3(-20.651,6.746)
  Bottom Layer w0.2: v3(-43.32,7.611) -43.32,7.559 -43.367,7.511 -43.367,7.142 -43,6.775 -40.05,6.775 -39.675,7.15 -39.675,9.146 -40.26,9.731 -40.26,14.807 -39.665,15.403 -39.665,15.74 -41.475,17.55 -41.475,18.367 -41.067,18.775 U104.1@-40.325,18.775 ; R121.1@-41.775,19.75 -40.8,19.75 -40.325,19.275 U104.1@-40.325,18.775 ; C118.2@-39.4,18.775 U104.1@-40.325,18.775
USIM_DET: CON102.CD D106.K U101.79 | length 34.7
  Layer 2 w0.15: v3@-45.475,15.1 -40.825,15.1 -40.3,14.575 -40.3,11.332 -39.494,10.526 -38.42,10.526 -38.079,10.867 -29.367,10.867 -27.888,9.388 -22.732,9.388 -22.444,9.1 -21.835,9.1 -20.797,8.063 -20.277,8.063 -19.233,9.106 v3(-19.233,10.539)
  Bottom Layer w0.15: D106.K@-45.725,17.075 D106.K@-45.695,17.045
  Bottom Layer w0.3: CON102.CD@-45.695,15.617 D106.K@-45.695,17.045
  other v3: -45.439,15.108
USIM_RST: CON102.2 U100.7 U101.12 U104.4 | length 32.3
  Layer 2 w0.2: v3(-42.157,13.216) -42.157,13.208 -42.239,13.126 -42.239,7.664 -41.262,6.687 -26.962,6.687 -26.44,6.165 -22.332,6.165 v3(-21.751,6.746)
  Bottom Layer w0.2: U104.4@-42.325,17.475 -42.325,17.35 -40.935,15.96 -40.935,14.79 -41.2,14.525 -41.9,14.525 -42.083,14.342 U100.7@-42.083,13.561
USIM_VDD: C116.2 CON102.1 R121.2 U100.8 U101.14 U104.5 | length 35.1
  Layer 2 w0.3: v3(-41.181,12.903) -41.175,12.898 -41.175,9.952 -39.473,8.25 -36.338,8.25 -35.488,9.1 -31.05,9.1 -30.279,8.329 v3@-23.329,8.329
  Bottom Layer w0.2: U101.14@-24.481,9.544 U101.14@-24.35,9.675
  Bottom Layer w0.25: CON102.1@-43.475,15.617 -43.475,14.957 -42.764,14.247 -42.764,12.989 -42.466,12.691 -42.422,12.691 -42.418,12.686 -41.398,12.686 v3(-41.181,12.903) ; v3@-41.181,12.908 -40.953,13.136 -40.888,13.136 -40.813,13.211 U100.8@-40.813,13.561
  Bottom Layer w0.3: CON102.1@-43.475,15.617 C116.2@-43.475,16.9 -43.475,18.35 -43.05,18.775 U104.5@-42.325,18.775 -42.325,19.725 R121.2@-42.3,19.75 ; U101.14@-24.35,9.675 -23.625,9.675 -23.325,9.375 v3@-23.325,8.35
  other v3: -23.325,8.325
VBAT: C102.1 C103.2 C104.2 C105.2 C113.2 C203.2 C218.1 C300.2 C304.2 CON300.3 D104.K D105.K Q100.S Q101.S R118.1 R119.1 TP105.1 U101.42 U101.43 U103.1 U201.6 U300.4 | length 42.1
  Top Layer w0.5: C304.2@-11.525,23.35 -11.512,23.363 -10.792,23.363 -10.079,24.075 -9.318,24.075 -9.025,24.368 -9.025,24.989 -8.2,25.814 -8.2,26.45 CON300.3@-8.05,26.6 ; U300.4@-10.945,12.7 -10.945,12.336 -10.922,12.313 C300.2@-9.775,12.313 -9.775,11.6 -10.214,11.161 -10.214,6.85 ; -10.625,6.439 -10.214,6.85 ; -10.214,6.212 -10.214,6.85 ; -10.2,6.85 -10.214,6.85 ; -9.45,6.086 -10.214,6.85
  Layer 1 w0.5: v1@-11.525,23.363 -11.525,20.45 -10.3,19.225 -10.3,13.075 -9.75,12.525 v1(-9.75,12.423) v1(-9.75,12.2)
  Layer 1 w0.8: v2(-35.75,19.632) -33.018,16.9 v1@-24.6,16.9
  Bottom Layer w0.6: U101.43@-8.15,10.775 -6.7,10.775 -6.675,10.75 ; U101.42@-8.15,11.875 -6.8,11.875 -6.75,11.825
  other v1: -24.9,16.675 -24.65,16.675 -24.9,16.975 -24.65,16.975 -11.55,23.225 -11.55,23.45
  other v2: -6.225,5.925 -5.7,5.925 -6.225,6.45 -5.7,6.45 -35.275,19.15
VBAT_Li: C111.2 CON101.1 Q100.D R113.2 U102.5 | length 3.8
  Top Layer w0.3: -27.308,17.775 -26.825,18.258 -26.825,18.375 ; CON101.1@-25,21.625 -24.927,21.698 -24.927,23.346 -24.466,23.806 -24.32,23.806 v2(-24.292,23.835)
  Bottom Layer w0.3: v2(-24.292,23.835) -24.251,23.835 -24.163,23.924 R113.2@-23.876,23.924
VBUS: C106.2 CON100.A4B9 CON100.B4A9 D103.K D104.A Q100.G R106.2 R110.1 R115.2 R302.2 R303.1 U101.61 U102.4 | length 32.3
  Top Layer w0.3: R110.1@-31.9,10.75 -31.9,10.3 -31.5,9.9 -30.744,9.9 ; Q100.G@-26.653,16.75 -26.417,16.986 -26.417,17.733 v1(-26.225,17.925)
  Top Layer w0.5: CON100.A4B9@-36,6.363 -35.95,6.313 -35.95,5.476 -35.715,5.241 -35.715,4.585 -35.28,4.15 v2(-35.15,4.15) v2(-32.8,4.15) -32.574,4.15 -31.25,5.474 -31.25,6.263 -31.15,6.363 -31.15,7.3 -30.8,7.65
  Layer 1 w0.3: v1(-32.675,19.2) -32.162,18.687 -27.881,18.687 -27.53,19.038 -26.401,19.038 -26.225,18.862 ; v1@-26.225,17.927 -26.225,18.862 ; v2(-18.67,19.921) -19.729,18.862 -26.225,18.862
  Bottom Layer w0.3: v2(-18.67,19.921) -18.66,19.911 U101.61@-18.66,19.312
  Bottom Layer w0.5: R302.2@-35.15,2.55 v2(-35.15,4.15) ; v2@-32.811,4.137 -32.811,3.586 -32.45,3.225 R303.1@-32.45,2.55
VCC5V: C205.2 C206.2 Q101.D U200.19 | length 37.4
  Top Layer w0.3: U200.19@-47.258,13.641 U200.19@-47.25,13.632
  Top Layer w0.4: C206.2@-48.4,13.6 v2(-46.25,13.6)
  Top Layer w0.5: C205.2@-46.425,6.8 v2(-46.425,7.575) ; C205.2@-46.4,6.8 -46.4,4.275 -45.2,3.075 -27.72,3.075 -26.625,4.17 -26.625,8.525 -26.15,9 -26.15,9.05 Q101.D@-26.1,9.05
  Layer 2 w0.5: v2(-46.425,7.575) -46.359,7.641 -46.359,13.491 v2(-46.25,13.6)
VDD_EXT: C110.2 C306.1 CON302.10 TP107.1 U101.24 | length 19.4
  Top Layer w0.3: v2@-20.654,23.413 -20.656,23.414 -20.656,23.472 -20.654,23.474 TP107.1@-20.654,24.397
  Layer 2 w0.3: v3(-31.675,24.4) -31.625,24.45 -21.732,24.45 v2(-20.685,23.403)
  Bottom Layer w0.3: C306.1@-31.975,20.575 -31.975,20.683 -31.7,20.958 CON302.10@-31.7,21.712 -31.7,24.375 v3(-31.675,24.4) ; U101.24@-21.75,21.225 -21.726,21.249 -21.726,22.149 -20.714,23.161 -20.714,23.348 v2@-20.662,23.4 ; v2(-20.685,23.403) -20.682,23.4 v2@-20.662,23.4 ; v2@-20.654,23.408 v2@-20.662,23.4 ; C110.2@-20.275,23.4 v2@-20.662,23.4
pads on no net: CON100. CON100.A8 CON100.B8 CON102.0@-39.405,2.482 CON102.0@-39.405,9.783 CON102.0@-41.945,2.482 CON102.0@-41.945,9.783 CON102.0@-44.485,2.482 CON102.0@-44.485,9.783 CON102.0@-44.485,13.483 CON102.6 CON302.0@-28.7,21.712 CON302.0@-29.2,21.712 CON302.0@-29.7,21.712 CON302.0@-30.2,21.712 CON302.0@-30.7,21.712 CON302.0@-31.2,21.712 CON302.0@-31.7,21.712 CON302.0@-32.2,21.712 CON302.0@-32.7,21.712 CON302.0@-33.2,21.712 CON302.0@-33.7,21.712 CON302.0@-34.2,21.712 CON302.0@-34.7,21.712 CON302.0@-35.2,21.712 CON302.0@-35.7,21.712 CON302.0@-36.2,21.712 D100. D101. D102. D103. D105. D106. D300. D301. D302. D303. D304. D305. K100.0@-19.225,2.8 K100.0@-21.525,2.8 LED300.1 M1.1 M2.1 Oil300.29 Q100. Q101. U100. U100.0 U100.2 U100.4 U100.5 U101.2 U101.3 U101.4 U101.8 U101.9 U101.26 U101.30 U101.31 U101.32 U101.33 U101.44 U101.65 U101.66 U101.68 U101.69 U101.74 U101.75 U101.76 U101.77 U101.81 U101.83 U101.84 U101.85 U101.86 U101.97 U101.98 U101.99 U101.102 U101.104 U101.105 U101.106 U101.107 U101.108 U101.109 U102. U200. U200.1 U200.2 U200.4 U200.6 U200.8 U200.22 U200.23 U201. U202. U300. U300.1

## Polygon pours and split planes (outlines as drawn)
AGND on Top Layer "T-AGND" (solid, remove dead copper, pour order 2): -44.582,7.237 -44.025,7.793 -44.025,18.125 -43.975,18.175 -42.15,18.175 -40.85,19.475 -40.85,25.096 -40.865,25.11 -40.865,26.465 -41.475,27.075 -49.725,27.075 -50.75,26.05 -50.75,7.237
AGND on Top Layer "G1--AGND" (solid, remove dead copper, pour order 9): -44.582,7.237 -44.025,7.793 -44.025,17.65 -43.525,18.15 -42.175,18.15 -40.85,19.475 -40.85,25.096 -40.865,25.11 -40.865,26.465 -41.475,27.075 -49.725,27.075 -50.75,26.05 -50.75,7.237
GND on Top Layer "T-GND" (solid, remove dead copper, pour order 7): -52,4 ccw(c-48,4) -48,0 -4,0 ccw(c-4,4) 0,4 0,31.8 -16,31.8 -16,27.8 -36,27.8 -36,31.8 -52,31.8
GND on Layer 1 "T-GND" (solid, remove dead copper, pour order 6): -52,4 ccw(c-48,4) -48,0 -4,0 ccw(c-4,4) 0,4 0,31.8 -16,31.8 -16,27.8 -36,27.8 -36,31.8 -52,31.8
AGND on Layer 1 "G1--AGND" (solid, remove dead copper, pour order 3): -44.582,7.237 -44.025,7.793 -44.025,17.65 -43.525,18.15 -42.175,18.15 -40.85,19.475 -40.85,25.096 -40.865,25.11 -40.865,26.465 -41.475,27.075 -49.725,27.075 -50.75,26.05 -50.75,7.237
GND on Bottom Layer "T-GND" (solid, remove dead copper, pour order 5): -52,4 ccw(c-48,4) -48,0 -4,0 ccw(c-4,4) 0,4 0,31.8 -16,31.8 -16,27.8 -36,27.8 -36,31.8 -52,31.8
GND on Layer 2 "T-GND" (solid, remove dead copper, pour order 4): -52.051,3.954 ccw(c-48.051,3.954) -48.051,-0.046 -4.051,-0.046 ccw(c-4.051,3.954) -0.051,3.954 -0.051,31.754 -16.051,31.754 -16.051,27.754 -36.051,27.754 -36.051,31.754 -52.051,31.754

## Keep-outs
Keep-Out Layer:
  the board outline again, w0.2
